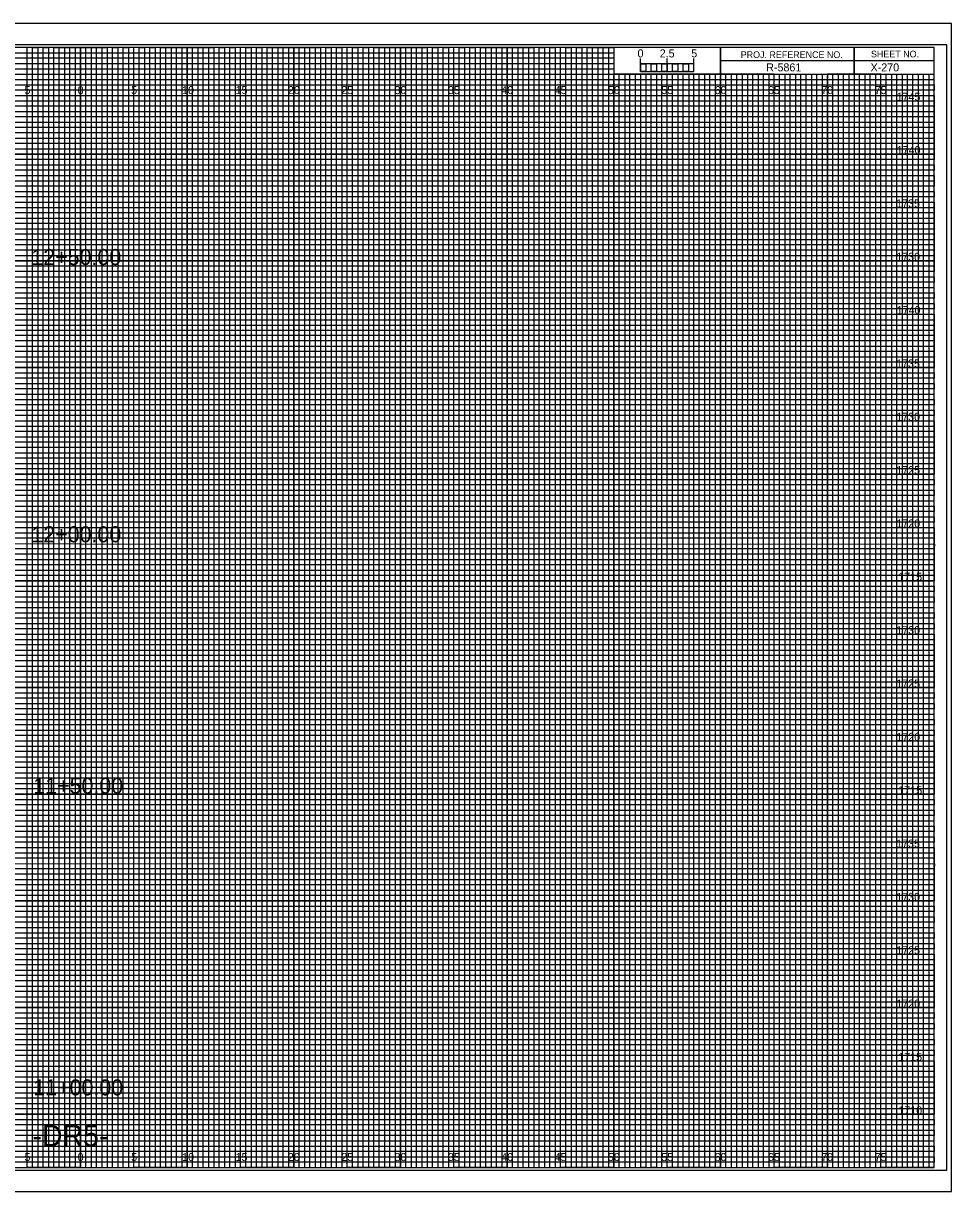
# Model space of a CAD drawing. Extents: x -7 to 162, y -2 to 107.
# Drawn here: x 74.6 to 161.7, y -2.3 to 107.3 of the extents above; entities that cross this region are included whole.
import ezdxf

# ---------------------------------------------------------------- set-up
doc = ezdxf.new("R2010")
doc.units = 0
for name, color, linetype in [('Prop Horizontal Alignment', 7, 'Continuous'), ('Prop XS Alignment Label', 7, 'Continuous'), ('Prop XS Bar Scale Labels', 7, 'Continuous'), ('Prop XS Project Number', 7, 'Continuous'), ('Prop XS Sheet Number', 7, 'Continuous'), ('Raster_Level_0', 7, 'Continuous'), ('Scratch_Level_3', 7, 'Continuous'), ('Sheet Cross Section CELL', 7, 'Continuous'), ('Sheet Cross Section Grid Major CELL', 7, 'Continuous'), ('Sheet Cross Section Grid Middle CELL', 7, 'Continuous'), ('Sheet Cross Section Grid Minor 1 CELL', 7, 'Continuous'), ('Sheet Cross Section Grid Minor 2 CELL', 7, 'Continuous'), ('Sheet Cross Section Scale CELL', 7, 'Continuous'), ('Sheet Cutting Line CELL', 7, 'Continuous'), ('Sheet DOT Grid CELL', 7, 'Continuous'), ('Sheet Plot Border Inside CELL', 7, 'Continuous'), ('Sheet Plot Border Outside CELL', 7, 'Continuous')]:
    doc.layers.add(name, color=color, linetype=linetype)

msp = doc.modelspace()

# ---------------------------------------------------------------- linework, layer by layer
at = {"layer": 'Sheet Cross Section CELL'}
for p, q in [((152.5, 105), (152.5, 102.5)), ((152.5, 102.5), (152.5, 105)), ((160, 103.75), (140, 103.75)), ((140, 103.75), (140, 102.5)), ((140, 102.5), (160, 102.5))]:
    msp.add_line(p, q, dxfattribs=at)
for points in [[(160, 105), (0, 105), (0, 0), (160, 0)], [(140, 105), (130, 105), (130, 102.52), (140, 102.52)], [(160, 105), (140, 105), (140, 102.5), (160, 102.5)]]:
    msp.add_lwpolyline(points, close=True, dxfattribs=at)
at = {"layer": 'Sheet Cross Section Grid Major CELL'}
for p, q in [((75, 105), (70, 105)), ((75, 0), (75, 105)), ((85, 105), (80, 105)), ((80, 105), (80, 0)), ((85, 0), (85, 105)), ((95, 105), (90, 105)), ((90, 105), (90, 0)), ((95, 0), (95, 105)), ((105, 105), (100, 105)), ((100, 105), (100, 0)), ((105, 0), (105, 105)), ((115, 105), (110, 105)), ((110, 105), (110, 0)), ((115, 0), (115, 105)), ((125, 105), (120, 105)), ((120, 105), (120, 0)), ((125, 0), (125, 105)), ((130, 105), (130, 0)), ((135, 0), (135, 102.5)), ((145, 102.5), (140, 102.5)), ((140, 102.5), (140, 0)), ((145, 0), (145, 102.5)), ((155, 102.5), (150, 102.5)), ((150, 102.5), (150, 0)), ((155, 0), (155, 102.5)), ((80, 0), (75, 0)), ((90, 0), (85, 0)), ((100, 0), (95, 0)), ((110, 0), (105, 0)), ((120, 0), (115, 0)), ((130, 0), (125, 0)), ((140, 0), (135, 0)), ((150, 0), (145, 0)), ((160, 0), (155, 0)), ((160, 0), (160, 0))]:
    msp.add_line(p, q, dxfattribs=at)
for points in [[(0, 100), (160, 100), (160, 95), (0, 95)], [(0, 90), (160, 90), (160, 85), (0, 85)], [(0, 80), (160, 80), (160, 75), (0, 75)], [(0, 70), (160, 70), (160, 65), (0, 65)], [(0, 60), (160, 60), (160, 55), (0, 55)], [(0, 50), (160, 50), (160, 45), (0, 45)], [(0, 40), (160, 40), (160, 35), (0, 35)], [(0, 30), (160, 30), (160, 25), (0, 25)], [(0, 20), (160, 20), (160, 15), (0, 15)], [(0, 10), (160, 10), (160, 5), (0, 5)]]:
    msp.add_lwpolyline(points, dxfattribs=at)
at = {"layer": 'Sheet Cross Section Grid Middle CELL'}
for points in [[(72.5, 0), (77.5, 0), (77.5, 105), (82.5, 105), (82.5, 0), (87.5, 0), (87.5, 105), (92.5, 105), (92.5, 0), (97.5, 0), (97.5, 105), (102.5, 105), (102.5, 0), (107.5, 0), (107.5, 105), (112.5, 105), (112.5, 0), (117.5, 0), (117.5, 105), (122.5, 105), (122.5, 0), (127.5, 0), (127.5, 105), (129.97, 105), (130, 105), (130, 102.5), (132.5, 102.5), (132.5, 0), (137.5, 0), (137.5, 102.5), (142.5, 102.5), (142.5, 0), (147.5, 0), (147.5, 102.5), (152.5, 102.5), (152.5, 0), (157.5, 0), (157.5, 102.5)], [(0, 102.5), (137.5, 102.5)], [(0, 92.5), (160, 92.5), (160, 97.5), (0, 97.5)], [(0, 82.5), (160, 82.5), (160, 87.5), (0, 87.5)], [(0, 72.5), (160, 72.5), (160, 77.5), (0, 77.5)], [(0, 62.5), (160, 62.5), (160, 67.5), (0, 67.5)], [(0, 52.5), (160, 52.5), (160, 57.5), (0, 57.5)], [(0, 42.5), (160, 42.5), (160, 47.5), (0, 47.5)], [(0, 32.5), (160, 32.5), (160, 37.5), (0, 37.5)], [(0, 22.5), (160, 22.5), (160, 27.5), (0, 27.5)], [(0, 12.5), (160, 12.5), (160, 17.5), (0, 17.5)], [(0, 2.5), (160, 2.5), (160, 7.5), (0, 7.5)]]:
    msp.add_lwpolyline(points, dxfattribs=at)
at = {"layer": 'Sheet Cross Section Grid Minor 1 CELL'}
for p, q in [((0, 104.5), (130, 104.5)), ((130, 104.5), (130, 103.99)), ((130, 103.99), (0, 103.99)), ((0, 103.5), (130, 103.5)), ((130, 102.95), (0, 102.95)), ((130, 103.5), (130, 102.95)), ((0, 102), (160, 102))]:
    msp.add_line(p, q, dxfattribs=at)
for points in [[(0, 101.5), (135, 101.5), (160, 101.5), (160, 101), (0, 101)], [(0, 100.5), (160, 100.5), (160, 99.5), (0, 99.5)], [(0, 99), (160, 99), (160, 98.5), (0, 98.49)], [(0, 98), (160, 98), (160, 97), (0, 97)], [(0, 96.5), (160, 96.5), (160, 96), (0, 96)], [(0, 95.5), (160, 95.5), (160, 94.5), (0, 94.5)], [(0, 94), (160, 94), (160, 93.5), (0, 93.5)], [(0, 93), (160, 93), (160, 92), (0, 92)], [(0, 91.5), (160, 91.5), (160, 91), (0, 91)], [(0, 90.5), (160, 90.5), (160, 89.5), (0, 89.5)], [(0, 89), (160, 89), (160, 88.5), (0, 88.5)], [(0, 88), (160, 88), (160, 86.98), (160, 86.5), (160, 86), (0, 86)], [(0, 87), (160, 87), (160, 86.5), (0, 86.5)], [(0, 85.5), (160, 85.5), (160, 84.5), (0, 84.52)], [(0, 84.52), (160, 84.5), (160, 84), (0, 84)], [(0, 83.5), (160, 83.5), (160, 83), (0, 83)], [(0, 82), (160, 82), (160, 81.5), (0, 81.5)], [(0, 81), (160, 81), (160, 80.5), (0, 80.5)], [(-0.04, 79.45), (160, 79.45), (160, 78.94), (-0.04, 78.94)], [(0, 78.5), (160, 78.5), (160, 78), (0, 78)], [(0, 77), (160, 77), (160, 76.5), (0, 76.5)], [(0, 76), (160, 76), (160, 75.5), (0, 75.5)], [(0, 74.5), (160, 74.5), (160, 74), (0, 74)], [(0, 73.5), (160, 73.5), (160, 73), (0, 73)], [(0, 72), (160, 72), (160, 71.5), (0, 71.5)], [(0, 71), (160, 71), (160, 70.5), (0, 70.5)], [(0, 69.5), (160, 69.5), (160, 68.99), (0, 69)], [(0, 68.5), (160, 68.5), (160, 68), (0, 68)], [(0, 67), (160, 67), (160, 66.5), (0, 66.5)], [(0, 66), (160, 66), (160, 65.5), (0, 65.5)], [(0, 64.5), (160, 64.5), (160, 64), (0, 64)], [(0, 63.5), (160, 63.5), (160, 63), (0, 63)], [(0, 62), (160, 62), (160, 61.5), (0, 61.5)], [(0, 61), (160, 61), (160, 60.5), (0, 60.5)], [(0, 59.5), (160, 59.5), (160, 59), (0, 59)], [(0, 58.5), (160.03, 58.45), (160, 58), (0, 58)], [(0, 57), (160, 57), (160, 56.5), (0, 56.5)], [(0, 56), (160, 56), (160, 55.5), (0, 55.5)], [(0, 54.5), (160, 54.5), (160, 54), (0, 54)], [(0, 53.5), (160, 53.5), (160, 53), (0, 53)], [(0, 52), (160, 52), (160, 51.5), (0, 51.5)], [(0, 51), (160, 51), (160, 50.5), (0, 50.5)], [(0, 49.5), (160, 49.5), (160, 49), (0, 49)], [(0, 48.5), (160, 48.5), (160, 48), (0, 48)], [(0, 47), (160, 47), (160, 46.5), (0, 46.5)], [(0, 46), (160, 46), (160, 45.5), (0, 45.5)], [(0, 44.5), (160, 44.5), (160, 44), (0, 44)], [(0, 43.5), (160, 43.5), (160, 43), (0, 43)], [(0, 42), (160, 42), (160, 41.5), (0, 41.5)], [(0, 41), (160, 41), (160, 40.5), (0, 40.5)], [(0, 39.5), (160, 39.5), (160, 38.99), (0, 39)], [(0, 38.5), (160, 38.5), (160, 38), (0, 38)], [(0, 37), (160, 37), (160, 36.5), (0, 36.5)], [(0, 36), (160, 36), (160, 35.5), (0, 35.5)], [(0, 34.5), (160, 34.5), (160, 34), (0, 34)], [(0, 33.5), (160, 33.5), (160, 33), (0, 33)], [(0, 32), (160, 32), (160, 31.5), (0, 31.5)], [(0, 31), (160, 31), (160, 30.5), (0, 30.5)], [(0, 29.5), (160, 29.5), (160, 29), (0, 29)], [(0, 28.5), (160.03, 28.46), (160, 28), (0, 28)], [(0, 27), (160, 27), (160, 26.5), (0, 26.5)], [(0, 26), (160, 26), (160, 25.5), (0, 25.5)], [(0, 24.5), (160, 24.5), (160, 24), (0, 24)], [(0, 23.5), (160, 23.5), (160, 23), (0, 23)], [(0, 22), (160, 22), (160, 21.5), (0, 21.5)], [(0, 21), (160, 21), (160, 20.5), (0, 20.5)], [(0, 19.5), (160, 19.5), (160, 19), (0, 19)], [(0, 18.5), (160, 18.5), (160, 18), (0, 18)], [(0, 17), (160, 17), (160, 16.5), (0, 16.5)], [(0, 16), (160, 16), (160, 15.5), (0, 15.5)], [(0, 14.5), (160, 14.5), (160, 14), (0, 14)], [(0, 13.5), (160, 13.5), (160, 13), (0, 13)], [(0, 12), (160, 12), (160, 11.5), (0, 11.5)], [(0, 11), (160, 11), (160, 10.5), (0, 10.5)], [(0, 9.5), (160, 9.5), (160, 9), (0, 9)], [(0, 8.5), (160, 8.5), (160, 8), (0, 8)], [(0, 7), (160, 7), (160, 6.5), (0, 6.5)], [(0, 6), (160, 6), (160, 5.5), (0, 5.5)], [(0, 4.5), (160, 4.5), (160, 4), (0, 4)], [(0, 3.5), (160, 3.5), (160, 3), (0, 3)], [(0, 2), (160, 2), (160, 1.5), (0, 1.5)], [(0, 1), (160, 1), (160, 0.5), (0, 0.5)]]:
    msp.add_lwpolyline(points, dxfattribs=at)
at = {"layer": 'Sheet Cross Section Grid Minor 2 CELL'}
for p, q in [((133.5, 102.5), (133, 102.5)), ((133, 102.5), (133, 0)), ((133.5, 0), (133.5, 102.5)), ((134.5, 102.5), (134, 102.5)), ((134, 102.5), (134, 0)), ((134.5, 0), (134.5, 102.5)), ((133, 0), (132.5, 0)), ((134, 0), (133.5, 0))]:
    msp.add_line(p, q, dxfattribs=at)
for points in [[(75, 0), (75.5, 0), (75.5, 105), (76, 105), (76, 0)], [(76, 0), (76.5, 0), (76.5, 105), (77, 105), (77, 0)], [(77.5, 0), (78, 0), (78, 105), (78.5, 105), (78.5, 0)], [(78.5, 0), (79, 0), (79, 105), (79.5, 105), (79.5, 0)], [(80, 0), (80.5, 0), (80.5, 105), (81, 105), (81, 0)], [(81, 0), (81.5, 0), (81.5, 105), (82, 105), (82, 0)], [(82.5, 0), (83, 0), (83, 105), (83.5, 105), (83.5, 0)], [(83.5, 0), (84, 0), (84, 105), (84.5, 105), (84.5, 0)], [(85, 0), (85.5, 0), (85.5, 105), (86, 105), (86, 0)], [(86, 0), (86.5, 0), (86.5, 105), (87, 105), (87, 0)], [(87.5, 0), (88, 0), (88, 105), (88.5, 105), (88.5, 0)], [(88.5, 0), (89, 0), (89, 105), (89.5, 105), (89.5, 0)], [(90, 0), (90.5, 0), (90.5, 105), (91, 105), (91, 0)], [(91, 0), (91.5, 0), (91.5, 105), (92, 105), (92, 0)], [(92.5, 0), (93, 0), (93, 105), (93.5, 105), (93.5, 0)], [(93.5, 0), (94, 0), (94, 105), (94.5, 105), (94.5, 0)], [(95, 0), (95.5, 0), (95.5, 105), (96, 105), (96, 0)], [(96, 0), (96.5, 0), (96.5, 105), (97, 105), (97, 0)], [(97.5, 0), (98, 0), (98, 105), (98.5, 105), (98.5, 0)], [(98.5, 0), (99, 0), (99, 105), (99.5, 105), (99.5, 0)], [(100, 0), (100.5, 0), (100.5, 105), (101, 105), (101, 0)], [(101, 0), (101.5, 0), (101.5, 105), (102, 105), (102, 0)], [(102.5, 0), (103, 0), (103, 105), (103.5, 105), (103.5, 0)], [(103.5, 0), (104, 0), (104, 105), (104.5, 105), (104.5, 0)], [(105, 0), (105.5, 0), (105.5, 105), (106, 105), (106, 0)], [(106, 0), (106.5, 0), (106.5, 105), (107, 105), (107, 0)], [(107.5, 0), (108, 0), (108, 105), (108.5, 105), (108.5, 0)], [(108.5, 0), (109, 0), (109, 105), (109.5, 105), (109.5, 0)], [(110, 0), (110.5, 0), (110.5, 105), (111, 105), (111, 0)], [(111, 0), (111.5, 0), (111.5, 105), (112, 105), (112, 0)], [(112.5, 0), (113, 0), (113, 105), (113.5, 105), (113.5, 0)], [(113.5, 0), (114, 0), (114, 105), (114.5, 105), (114.5, 0)], [(115, 0), (115.5, 0), (115.5, 105), (116, 105), (116, 0)], [(116, 0), (116.5, 0), (116.5, 105), (117, 105), (117, 0)], [(117.5, 0), (118, 0), (118, 105), (118.5, 105), (118.5, 0)], [(118.5, 0), (119, 0), (119, 105), (119.5, 105), (119.5, 0)], [(120, 0), (120.5, 0), (120.5, 105), (121, 105), (121, 0)], [(121, 0), (121.5, 0), (121.5, 105), (122, 105), (122, 0)], [(122.5, 0), (123, 0), (123, 105), (123.5, 105), (123.5, 0)], [(123.5, 0), (124, 0), (124, 105), (124.5, 105), (124.5, 0)], [(125, 0), (125.5, 0), (125.5, 105), (126, 105), (126, 0)], [(126, 0), (126.5, 0), (126.5, 105), (127, 105), (127, 0)], [(127.5, 0), (128, 0), (128, 105), (128.5, 105), (128.5, 0)], [(128.5, 0), (129, 0), (129, 105), (129.5, 105), (129.5, 0)], [(130, 0), (130.5, 0), (130.5, 102.5), (131.01, 102.5), (131.01, 0)], [(131, 0), (131.5, 0), (131.5, 102.5), (132, 102.5), (132, 0)], [(135, 0), (135.49, 0), (135.49, 102.5), (136, 102.5), (136, 0)], [(136, 0), (136.5, 0), (136.5, 102.5), (137.03, 102.5), (137.03, 0)], [(137.5, 0), (138, 0), (138, 102.5), (138.5, 102.5), (138.5, 0)], [(138.5, 0), (139, 0), (139, 102.5), (139.5, 102.5), (139.5, 0)], [(140, 0), (140.5, 0), (140.5, 102.5), (141, 102.5), (141, 0)], [(141, 0), (141.5, 0), (141.5, 102.5), (142, 102.5), (142, 0)], [(142.5, 0), (143, 0), (143, 102.5), (143.5, 102.5), (143.5, 0)], [(143.5, 0), (144, 0), (144, 102.5), (144.5, 102.5), (144.5, 0)], [(145, 0), (145.5, 0), (145.5, 102.5), (146, 102.5), (146, 0)], [(146, 0), (146.5, 0), (146.5, 102.5), (147, 102.5), (147, 0)], [(147.5, 0), (148, 0), (148, 102.5), (148.5, 102.5), (148.5, 0)], [(148.5, 0), (149, 0), (149, 102.5), (149.5, 102.5), (149.5, 0)], [(150, 0), (150.5, 0), (150.5, 102.5), (151, 102.5), (151, 0)], [(151, 0), (151.5, 0), (151.5, 102.5), (152, 102.5), (152, 0)], [(152.5, 0), (153, 0), (153, 102.5), (153.5, 102.5), (153.5, 0)], [(153.5, 0), (154, 0), (154, 102.5), (154.5, 102.5), (154.5, 0)], [(155, 0), (155.5, 0), (155.5, 102.5), (156, 102.5), (156, 0)], [(156, 0), (156.5, 0), (156.5, 102.5), (157, 102.5), (157, 0)], [(157.5, 0), (158, 0), (158, 102.5), (158.5, 102.5), (158.5, 0)], [(158.5, 0), (159, 0), (159, 102.5), (159.5, 102.5), (159.5, 0)]]:
    msp.add_lwpolyline(points, dxfattribs=at)
at = {"layer": 'Sheet Cross Section Scale CELL'}
for p, q in [((132.5, 102.75), (132.5, 103.95)), ((132.5, 103.45), (132.5, 103.95)), ((135, 102.75), (135, 103.95)), ((137.5, 102.75), (137.5, 103.95)), ((137.5, 103.45), (137.5, 103.95))]:
    msp.add_line(p, q, dxfattribs=at)
for points in [[(137.5, 103.45), (132.5, 103.45), (132.5, 102.75), (137.5, 102.75)], [(132.5, 103.45), (133, 103.45), (133, 102.75), (132.5, 102.75)], [(133.5, 103.45), (134, 103.45), (134, 102.75), (133.5, 102.75)], [(134.5, 103.45), (135, 103.45), (135, 102.75), (134.5, 102.75)], [(135.5, 103.45), (136, 103.45), (136, 102.75), (135.5, 102.75)], [(136.5, 103.45), (137, 103.45), (137, 102.75), (136.5, 102.75)]]:
    msp.add_lwpolyline(points, close=True, dxfattribs=at)
at = {"layer": 'Sheet Cutting Line CELL'}
for p, q in [((161.65, 107.25), (-6.7, 107.25)), ((-6.7, -2.25), (161.65, -2.25))]:
    msp.add_line(p, q, dxfattribs=at)
at = {"layer": 'Sheet DOT Grid CELL'}
for p, q in [((75, 0), (75, 105)), ((80, 0), (80, 105)), ((85, 0), (85, 105)), ((90, 0), (90, 105)), ((95, 0), (95, 105)), ((100, 0), (100, 105)), ((105, 0), (105, 105)), ((110, 0), (110, 105)), ((115, 0), (115, 105)), ((120, 0), (120, 105)), ((125, 0), (125, 105)), ((130, 0), (130, 102.34)), ((135, 0), (135, 102.34)), ((140, 0), (140, 102.34)), ((145, 0), (145, 102.34)), ((150, 0), (150, 102.34)), ((155, 0), (155, 102.34)), ((0, 100), (160, 100)), ((0, 95), (160, 95)), ((0, 90), (160, 90)), ((0, 85), (160, 85)), ((0, 80), (160, 80)), ((0, 75), (160, 75)), ((0, 70), (160, 70)), ((0, 65), (160, 65)), ((0, 60), (160, 60)), ((0, 55), (160, 55)), ((0, 50), (160, 50)), ((0, 45), (160, 45)), ((0, 40), (160, 40)), ((0, 35), (160, 35)), ((0, 30), (160, 30)), ((0, 25), (160, 25)), ((0, 20), (160, 20)), ((0, 15), (160, 15)), ((0, 10), (160, 10)), ((0, 5), (160, 5))]:
    msp.add_line(p, q, dxfattribs=at)
at = {"layer": 'Sheet Plot Border Inside CELL'}
msp.add_lwpolyline([(-5.4, -0.25), (161.2, -0.25), (161.2, 105.25), (-5.4, 105.25)], close=True, dxfattribs=at)
at = {"layer": 'Sheet Plot Border Outside CELL'}
msp.add_lwpolyline([(-6.7, -2.25), (161.65, -2.25), (161.65, 107.25), (-6.7, 107.25)], close=True, dxfattribs=at)

# ---------------------------------------------------------------- texts
at = {"layer": 'Prop Horizontal Alignment'}
for s, p in [('12+50.00', (75.39, 84.6)), ('12+00.00', (75.39, 58.61)), ('11+50.00', (75.57, 35.05)), ('11+00.00', (75.57, 6.77))]:
    msp.add_text(s, height=1.5, dxfattribs=at).set_placement(p)
at = {"layer": 'Prop XS Alignment Label'}
msp.add_text('-DR5-', height=2, dxfattribs=at).set_placement((75.48, 2))
at = {"layer": 'Prop XS Bar Scale Labels'}
for s, p in [('2.5', (134.29, 104.06)), ('5', (137.24, 104.06))]:
    msp.add_text(s, height=0.75, dxfattribs=at).set_placement(p)
at = {"layer": 'Prop XS Project Number'}
msp.add_text('R-5861', height=0.75, dxfattribs=at).set_placement((144.27, 102.75))
at = {"layer": 'Prop XS Sheet Number'}
msp.add_text('X-270', height=0.75, dxfattribs=at).set_placement((154.05, 102.75))
at = {"layer": 'Raster_Level_0'}
for s, p in [('5', (74.74, 100.62)), ('0', (79.73, 100.62)), ('0', (79.73, 100.62)), ('5', (84.74, 100.62)), ('10', (89.52, 100.62)), ('15', (94.53, 100.62)), ('20', (99.43, 100.62)), ('25', (104.44, 100.62)), ('30', (109.43, 100.62)), ('35', (114.44, 100.62)), ('40', (119.43, 100.62)), ('45', (124.44, 100.62)), ('50', (129.43, 100.62)), ('55', (134.44, 100.62)), ('60', (139.43, 100.62)), ('65', (144.44, 100.62)), ('70', (149.43, 100.62)), ('75', (154.44, 100.62)), ('5', (74.74, 0.62)), ('0', (79.73, 0.62)), ('0', (79.73, 0.62)), ('5', (84.74, 0.62)), ('10', (89.52, 0.62)), ('15', (94.53, 0.62)), ('20', (99.43, 0.62)), ('25', (104.44, 0.62)), ('30', (109.43, 0.62)), ('35', (114.44, 0.62)), ('40', (119.43, 0.62)), ('45', (124.44, 0.62)), ('50', (129.43, 0.62)), ('55', (134.44, 0.62)), ('60', (139.43, 0.62)), ('65', (144.44, 0.62)), ('70', (149.43, 0.62)), ('75', (154.44, 0.62))]:
    msp.add_text(s, height=0.75, dxfattribs=at).set_placement(p)
at = {"layer": 'Scratch_Level_3'}
for s, p in [('1745', (156.49, 100)), ('1740', (156.5, 95)), ('1735', (156.45, 90)), ('1730', (156.46, 85)), ('1740', (156.5, 80)), ('1735', (156.45, 75)), ('1730', (156.46, 70)), ('1725', (156.46, 65)), ('1720', (156.47, 60)), ('1715', (156.65, 55)), ('1730', (156.46, 50)), ('1725', (156.46, 45)), ('1720', (156.47, 40)), ('1715', (156.65, 35)), ('1735', (156.45, 30)), ('1730', (156.46, 25)), ('1725', (156.46, 20)), ('1720', (156.47, 15)), ('1715', (156.65, 10)), ('1710', (156.66, 5))]:
    msp.add_text(s, height=0.75, dxfattribs=at).set_placement(p)
at = {"layer": 'Sheet Cross Section CELL'}
for s, p in [('PROJ. REFERENCE NO.', (141.88, 104)), ('SHEET NO.', (154.09, 104.06))]:
    msp.add_text(s, height=0.625, dxfattribs=at).set_placement(p)
at = {"layer": 'Sheet Cross Section Scale CELL'}
msp.add_text('0', height=0.75, dxfattribs=at).set_placement((132.21, 104.06))

doc.saveas('drawing.dxf')
